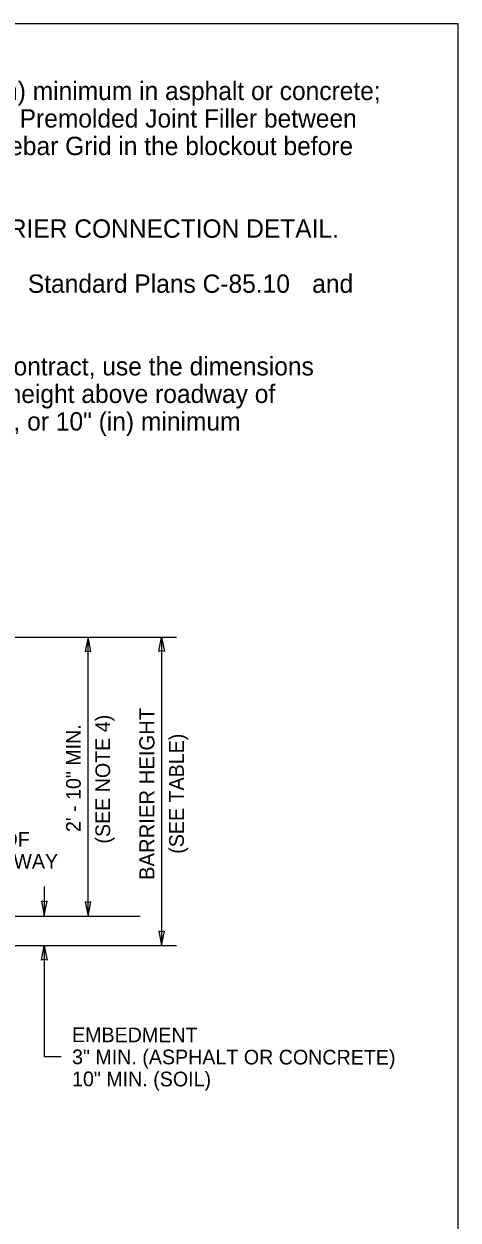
# Model space of a CAD drawing. Extents: x 99862 to 103680, y 99470 to 102076.
# Drawn here: x 102678 to 103151, y 100773 to 102076 of the extents above; entities that cross this region are included whole.
import ezdxf

# ---------------------------------------------------------------- set-up
doc = ezdxf.new("R2010")
doc.units = 0
for name, color, linetype in [('Level 1', 7, 'Continuous'), ('Level 15', 7, 'Continuous'), ('Level 16', 7, 'Continuous'), ('Level 20', 7, 'Continuous'), ('Level 60', 7, 'Continuous')]:
    doc.layers.add(name, color=color, linetype=linetype)

msp = doc.modelspace()

# ---------------------------------------------------------------- linework, layer by layer
at = {"layer": 'Level 1'}
msp.add_lwpolyline([(99862, 99999.5), (103151, 99999.5), (103151, 102075.5), (99862, 102075.5)], close=True, dxfattribs=at)
at = {"layer": 'Level 15'}
for p, q in [((102480, 101407.5), (102844.3, 101407.5)), ((102748, 101103.5), (102748, 101407.5)), ((102828, 101407.5), (102828, 101071.5)), ((102700.3, 101136), (102700.3, 101104.3)), ((102606.2, 101103.5), (102764, 101103.5)), ((102550, 101071.5), (102844.3, 101071.5)), ((102700.3, 101071.4), (102700.3, 100950.4)), ((102718.5, 100950.4), (102700.3, 100950.4))]:
    msp.add_line(p, q, dxfattribs=at)
for points in [[(102748, 101407.5), (102744.9, 101391.8), (102748, 101392.5), (102751.1, 101391.8)], [(102828, 101407.5), (102831.1, 101391.8), (102828, 101392.5), (102824.9, 101391.8)], [(102700.3, 101104.3), (102703.4, 101120), (102700.3, 101119.3), (102697.2, 101120)], [(102748, 101103.5), (102751.1, 101119.3), (102748, 101118.5), (102744.9, 101119.3)], [(102828, 101071.5), (102831.1, 101087.3), (102828, 101086.5), (102824.9, 101087.3)], [(102700.3, 101071.4), (102703.4, 101055.6), (102700.3, 101056.4), (102697.2, 101055.6)]]:
    msp.add_lwpolyline(points, close=True, dxfattribs=at)
at = {"layer": 'Level 16'}
msp.add_line((102804.9, 101103.3), (102531.7, 101103.3), dxfattribs=at)
at = {"layer": 'Level 60'}
msp.add_line((103151, 102075.5), (103151, 102075.5), dxfattribs=at)

# ---------------------------------------------------------------- texts
at = {"layer": 'Level 20'}
for s, height, p in [('PERMANENT INSTALLATION requirements: Embed barrier 3" (in) minimum in asphalt or concrete;', 20, (101889, 101992.6)), ('Embed barrier 10" (in) minimum in compacted soil; Install 3/8" (in) Premolded Joint Filler between ', 20, (101889, 101962.6)), ('segments; fill the Connection Blockout with grout, centering the Rebar Grid in the blockout before ', 20, (101889, 101932.6)), ('for REBAR GRID DETAIL and BARRIER CONNECTION DETAIL.', 20, (102241, 101842.6)), ('Standard Plans C-85.10', 20, (102682.4, 101782.6)), ('and ', 20, (102992.1, 101782.6)), ('is specified in the Contract, use the dimensions ', 20, (102434.9, 101692.6)), ('given in the H/P row in the DIMENSION TABLE, with a minimum height above roadway of ', 20, (101889, 101662.6)), ('3\' - 6" and a minimum embedment of 3" (in) in asphalt or concrete, or 10" (in) minimum ', 20, (101889, 101632.6)), ('TOP OF', 16, (102604.8, 101179.4)), ('ROADWAY', 16, (102604.8, 101155.4))]:
    msp.add_text(s, height=height, dxfattribs=at).set_placement(p)
for s, height, rotation, p in [('BARRIER HEIGHT', 16.5, 90, (102820.3, 101143)), ('(SEE NOTE 4)', 16, 90, (102772, 101182.7)), ('2\' - 10" MIN.', 16, 90, (102740, 101195.2)), ('(SEE TABLE)', 16, 90, (102852.3, 101171.6)), ('EMBEDMENT', 16, 359.9177, (102730.5, 100966.4)), ('3" MIN. (ASPHALT OR CONCRETE)', 16, 359.9177, (102730.5, 100942.4)), ('10" MIN. (SOIL)', 16, 359.9177, (102730.5, 100918.4))]:
    msp.add_text(s, height=height, rotation=rotation, dxfattribs=at).set_placement(p)

doc.saveas('drawing.dxf')
